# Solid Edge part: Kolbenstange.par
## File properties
Username: ahadarics
Dokumentum tartalom típus: 0
Author: ahadarics
Last saved by: ahadarics
Revision: 78
Sűrűség: 0,000 kg/m^3
Pontosság: 0,990
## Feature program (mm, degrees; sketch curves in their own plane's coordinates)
base feature "unnamed BaseFeature 1"
thread "unnamed Thread 1"
chamfer "Letörés_1" setback 0.7
sketch for "Kihúzás_1" plane through (54.25, 0, 0) normal (1, 0, 0) x-axis (0, -1, 0)
  circle centre (0, 0) radius 10
extrude "Kihúzás_1" add finite 26.5 along -normal
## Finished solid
Body 1: solid body, 13 faces, 23 edges, 12 vertices.
  Faces by surface: plane 9, cylinder 3, cone 1
  Edges by curve: line 12, circle 11
Bounding box of the edges (mm): 138.000 x 20.000 x 20.000, from (-83.75, -10, -10) to (54.25, 10, 10).
Cylindrical faces by radius (mm): R4 x2, R10 x1
Conical faces (half-angle, radius in mm at the cone's reference point): 45 deg R3.3 x1
Planar faces by outward normal: +x 3, +z 1, -x 4, -z 1
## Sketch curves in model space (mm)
circle centre (54.25, 0, 0) radius 10
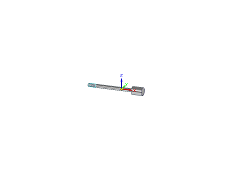
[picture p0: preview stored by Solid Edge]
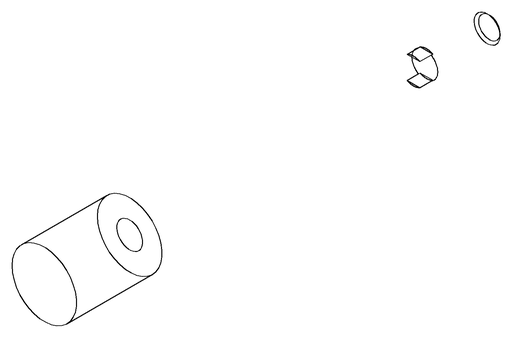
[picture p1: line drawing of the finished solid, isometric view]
